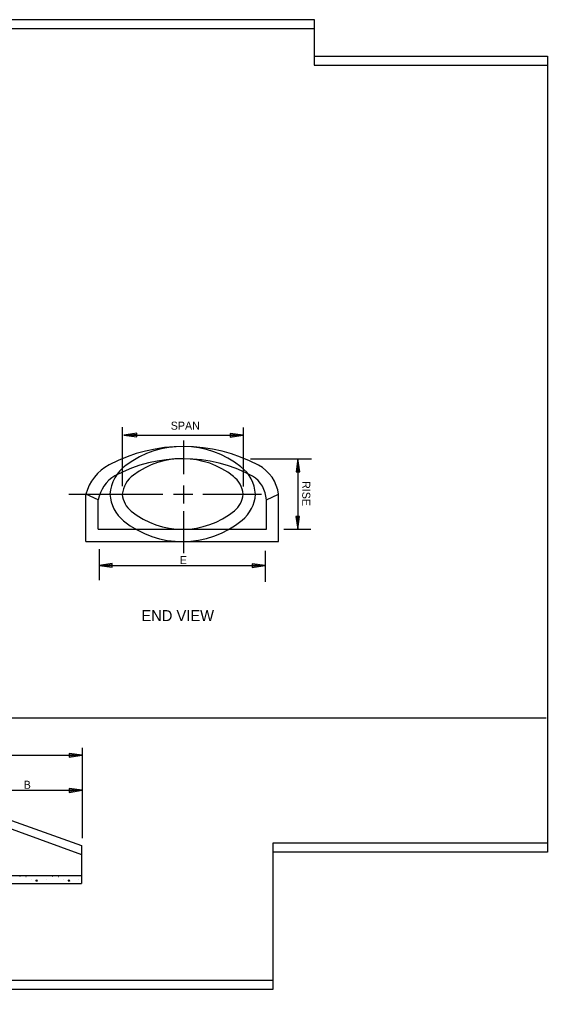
# Model space of a CAD drawing. Extents: x 0 to 390, y 0 to 265.
# Drawn here: x 245.7 to 390, y 0 to 265 of the extents above; entities that cross this region are included whole.
import ezdxf

# ---------------------------------------------------------------- set-up
doc = ezdxf.new("R2010")
doc.units = 0
doc.layers.add('D_Details', color=7, linetype='Continuous')
doc.layers.add('Default', color=7, linetype='Continuous')

msp = doc.modelspace()

# ---------------------------------------------------------------- linework, layer by layer
at = {"layer": 'D_Details'}
for p, q in [((273.84, 153.66), (273.84, 137.54)), ((277.82, 151.98), (274.27, 151.43)), ((274.27, 151.43), (306.82, 151.43)), ((274.27, 151.43), (277.82, 150.97)), ((275.16, 151.43), (277.82, 151.73)), ((277.82, 151.22), (275.16, 151.43)), ((276.55, 151.45), (277.82, 151.6)), ((277.82, 151.35), (276.55, 151.45)), ((277.82, 150.97), (277.82, 151.98)), ((306.82, 151.43), (303.28, 151.88)), ((303.28, 151.88), (303.28, 150.87)), ((303.28, 151.63), (305.93, 151.43)), ((303.28, 151.5), (304.54, 151.4)), ((303.28, 150.87), (306.82, 151.43)), ((305.93, 151.43), (303.28, 151.12)), ((304.54, 151.4), (303.28, 151.25)), ((306.85, 153.5), (306.85, 137.38)), ((290.55, 149.99), (290.55, 140.74)), ((308.9, 145), (325.49, 145)), ((321.82, 145), (321.36, 141.46)), ((321.61, 141.46), (321.82, 144.12)), ((321.82, 145), (321.82, 125.72)), ((322.37, 141.46), (321.82, 145)), ((321.82, 144.12), (322.12, 141.46)), ((321.36, 141.46), (322.37, 141.46)), ((321.74, 141.46), (321.84, 142.72)), ((321.84, 142.72), (321.99, 141.46)), ((259.24, 135.3), (284.96, 135.3)), ((263.9, 122.37), (263.9, 135.3)), ((267.26, 133.77), (263.9, 135.3)), ((287.83, 135.3), (293.13, 135.3)), ((290.55, 137.65), (290.55, 132.74)), ((295.81, 135.3), (311.84, 135.3)), ((313.2, 133.77), (316.55, 135.3)), ((316.55, 122.37), (316.55, 135.3)), ((267.26, 125.72), (267.26, 133.77)), ((313.2, 125.72), (313.2, 133.77)), ((290.55, 130.7), (290.55, 119.17)), ((322.27, 129.26), (321.26, 129.26)), ((321.26, 129.26), (321.82, 125.72)), ((321.82, 126.61), (321.51, 129.26)), ((321.79, 128), (321.64, 129.26)), ((321.89, 129.26), (321.79, 128)), ((321.82, 125.72), (322.27, 129.26)), ((322.02, 129.26), (321.82, 126.61)), ((267.26, 125.72), (313.2, 125.72)), ((290.55, 124.94), (290.55, 122.37)), ((317.99, 125.72), (325.33, 125.72)), ((263.9, 122.37), (316.55, 122.37)), ((267.57, 120.29), (267.57, 111.83)), ((312.88, 119.81), (312.88, 111.35)), ((271.12, 116.38), (267.57, 115.82)), ((267.57, 115.82), (312.88, 115.82)), ((267.57, 115.82), (271.12, 115.37)), ((268.46, 115.82), (271.12, 116.12)), ((271.12, 115.62), (268.46, 115.82)), ((269.85, 115.85), (271.12, 116)), ((271.12, 115.75), (269.85, 115.85)), ((271.12, 115.37), (271.12, 116.38)), ((312.88, 115.82), (309.34, 116.28)), ((309.34, 116.28), (309.34, 115.26)), ((309.34, 116.02), (312, 115.82)), ((309.34, 115.9), (310.61, 115.8)), ((309.34, 115.26), (312.88, 115.82)), ((312, 115.82), (309.34, 115.52)), ((310.61, 115.8), (309.34, 115.64)), ((-0.25, 74.24), (389.65, 74.24)), ((197.52, 64.06), (262.86, 64.06)), ((262.86, 64.06), (259.31, 64.52)), ((259.31, 64.52), (259.31, 63.5)), ((259.31, 64.26), (261.97, 64.06)), ((259.31, 64.14), (260.58, 64.03)), ((259.31, 63.5), (262.86, 64.06)), ((261.97, 64.06), (259.31, 63.76)), ((260.58, 64.03), (259.31, 63.88)), ((262.86, 66.02), (262.86, 41.39)), ((232.71, 54.44), (262.86, 54.44)), ((262.86, 54.44), (259.31, 54.89)), ((259.31, 54.89), (259.31, 53.88)), ((259.31, 54.64), (261.97, 54.44)), ((259.31, 54.52), (260.58, 54.41)), ((259.31, 53.88), (262.86, 54.44)), ((261.97, 54.44), (259.31, 54.14)), ((260.58, 54.41), (259.31, 54.26)), ((232.71, 50.04), (262.69, 39.33)), ((232.95, 47.75), (262.69, 36.86)), ((262.69, 39.33), (262.69, 29)), ((154.18, 31.12), (262.69, 31.12)), ((245.9, 30.97), (245.92, 30.97)), ((247.54, 30.89), (247.56, 30.89)), ((248.94, 30.13), (248.96, 30.13)), ((253.1, 30.15), (253.12, 30.15)), ((254.73, 30.97), (254.75, 30.97)), ((256.37, 30.89), (256.39, 30.89)), ((257.77, 30.13), (257.79, 30.13)), ((261.93, 30.15), (261.95, 30.15)), ((154.18, 29), (262.69, 29))]:
    msp.add_line(p, q, dxfattribs=at)
for points in [[(250.25, 29.64), (250.5, 29.95), (250.63, 29.62), (250.25, 29.64)], [(259.08, 29.64), (259.33, 29.95), (259.46, 29.62), (259.08, 29.64)]]:
    msp.add_lwpolyline(points, dxfattribs=at)
for centre, radius, start, end in [((290.55, 104.87), 43.48, 61.9084, 117.8155), ((290.31, 122.58), 25.77, 51.7543, 126.7229), ((290.65, 101.9), 46.45, 90, 90.00000277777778), ((276.17, 132.12), 12.67, 117.8155, 165.479), ((281.26, 134.5), 10.81, 126.0293, 175.7354), ((290.55, 104.87), 40.13, 61.9084, 117.8155), ((290.31, 122.58), 22.42, 51.7543, 126.7229), ((306.01, 133.84), 10.64, 7.8637, 61.9084), ((281.26, 134.5), 7.46, 126.0293, 174.0128), ((299.64, 134.55), 10.6, 4.0856, 51.3659), ((277, 131.9), 9.92, 121.4599, 169.1234), ((299.64, 134.55), 7.25, 5.867, 51.3659), ((304.95, 133.34), 8.26, 2.999, 57.0437), ((280.52, 135.88), 10.06, 183.3154, 231.0999), ((280.52, 135.88), 6.71, 185.1994, 231.0999), ((300.23, 135.92), 6.65, 309.3656, 354.5472), ((300.23, 135.92), 10, 309.3656, 356.4616), ((290.31, 148.02), 22.3, 231.0999, 309.3656), ((290.31, 148.02), 25.65, 231.0999, 309.3656)]:
    msp.add_arc(centre, radius, start, end, dxfattribs=at)
at = {"layer": 'Default'}
for points in [[(0, 265), (326.25, 265), (326.25, 255), (390, 255), (390, 37.5), (315, 37.5), (315, 0), (0, 0)], [(0, 262.5), (326.25, 262.5), (326.25, 252.5), (390, 252.5), (390, 40), (315, 40), (315, 2.5), (0, 2.5)]]:
    msp.add_lwpolyline(points, close=True, dxfattribs=at)

# ---------------------------------------------------------------- texts
at = {"layer": 'D_Details'}
for s, height, p in [('SPAN', 2.187, (287.07, 152.94)), ('E', 2.19, (289.53, 116.23)), ('END VIEW', 2.999, (279.06, 100.65)), ('B', 2.19, (246.91, 54.85))]:
    msp.add_text(s, height=height, dxfattribs=at).set_placement(p)
msp.add_text('RISE', height=2.187, rotation=270, dxfattribs=at).set_placement((322.99, 138.9))

doc.saveas('drawing.dxf')
